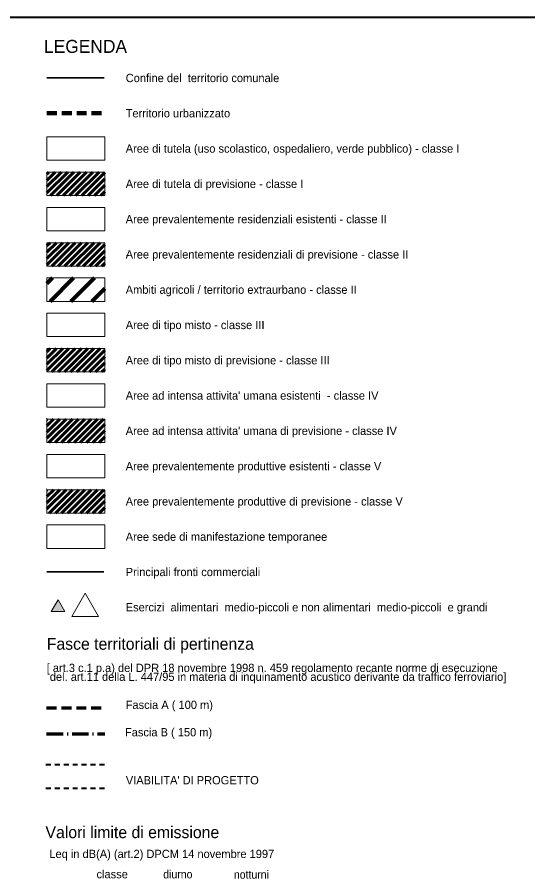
# Model space of a CAD drawing. Extents: x 650071 to 653841, y 889105 to 891996.
# Drawn here: x 651141 to 652006, y 890536 to 891996 of the extents above; entities that cross this region are included whole.
import ezdxf
from ezdxf.enums import TextEntityAlignment as Align

# ---------------------------------------------------------------- set-up
doc = ezdxf.new("R2010")
doc.units = 0
doc.header["$LTSCALE"] = 5.6
for name, pattern in [('DOT_DASHED', [7.7, 5, -1.2, 0.3, -1.2]), ('MEDIUM_DASHED', [4.5, 3, -1.5]), ('SHORT_DASHED', [2.7, 1.5, -1.2])]:
    doc.linetypes.add(name, pattern=pattern)
doc.layers.add('61', color=7, linetype='Continuous', lineweight=35)

msp = doc.modelspace()

# ---------------------------------------------------------------- hatches: boundary and pattern name
at = {"layer": '61'}
msp.add_hatch(color=256, dxfattribs=at).paths.add_polyline_path([(651209.89, 891008.04), (651221.26, 890988.36), (651198.51, 890988.36)])

# ---------------------------------------------------------------- linework, layer by layer
at = {"layer": '61', "lineweight": 40}
msp.add_line((651121.43, 891995.66), (652174.45, 891995.66), dxfattribs=at)
at = {"layer": '61'}
for p, q in [((651191.11, 891892.74), (651288.09, 891892.74)), ((651287.69, 891055.54), (651191.11, 891055.54))]:
    msp.add_line(p, q, dxfattribs=at)
at = {"layer": '61', "linetype": 'MEDIUM_DASHED', "lineweight": 100}
msp.add_line((651191.11, 891832.92), (651288.77, 891832.92), dxfattribs=at)
at = {"layer": '61', "lineweight": 60}
for p, q in [((651191.11, 891729.77), (651194.46, 891733.12)), ((651191.11, 891719.17), (651205.06, 891733.12)), ((651191.11, 891708.56), (651215.67, 891733.12)), ((651191.11, 891697.95), (651226.28, 891733.12)), ((651197.28, 891693.52), (651236.88, 891733.12)), ((651207.89, 891693.52), (651247.49, 891733.12)), ((651218.5, 891693.52), (651258.1, 891733.12)), ((651229.1, 891693.52), (651268.7, 891733.12)), ((651239.71, 891693.52), (651279.31, 891733.12)), ((651250.32, 891693.52), (651289.03, 891732.24)), ((651260.92, 891693.52), (651289.03, 891721.63)), ((651271.53, 891693.52), (651289.03, 891711.02)), ((651282.14, 891693.52), (651289.03, 891700.42)), ((651191.11, 891608), (651196.66, 891613.54)), ((651191.11, 891597.4), (651207.25, 891613.54)), ((651191.11, 891586.81), (651217.84, 891613.54)), ((651191.11, 891576.22), (651228.43, 891613.54)), ((651199.43, 891573.94), (651239.03, 891613.54)), ((651210.02, 891573.94), (651249.62, 891613.54)), ((651220.61, 891573.94), (651260.21, 891613.54)), ((651231.2, 891573.94), (651270.8, 891613.54)), ((651241.79, 891573.94), (651281.39, 891613.54)), ((651252.39, 891573.94), (651289.03, 891610.58)), ((651262.98, 891573.94), (651289.03, 891599.99)), ((651273.57, 891573.94), (651289.03, 891589.4)), ((651284.16, 891573.94), (651289.03, 891578.81)), ((651191.11, 891428.62), (651196.63, 891434.14)), ((651191.11, 891418.03), (651207.22, 891434.14)), ((651191.11, 891407.44), (651217.81, 891434.14)), ((651191.11, 891396.84), (651228.41, 891434.14)), ((651199.4, 891394.54), (651239, 891434.14)), ((651209.99, 891394.54), (651249.59, 891434.14)), ((651220.58, 891394.54), (651260.18, 891434.14)), ((651231.18, 891394.54), (651270.78, 891434.14)), ((651241.77, 891394.54), (651281.37, 891434.14)), ((651252.36, 891394.54), (651289.03, 891431.21)), ((651262.95, 891394.54), (651289.03, 891420.62)), ((651273.55, 891394.54), (651289.03, 891410.02)), ((651284.14, 891394.54), (651289.03, 891399.43)), ((651191.11, 891313.86), (651191.79, 891314.54)), ((651191.11, 891303.27), (651202.38, 891314.54)), ((651191.11, 891292.68), (651212.97, 891314.54)), ((651191.11, 891282.09), (651223.56, 891314.54)), ((651194.56, 891274.94), (651234.16, 891314.54)), ((651205.15, 891274.94), (651244.75, 891314.54)), ((651215.74, 891274.94), (651255.34, 891314.54)), ((651226.33, 891274.94), (651265.93, 891314.54)), ((651236.93, 891274.94), (651276.53, 891314.54)), ((651247.52, 891274.94), (651287.12, 891314.54)), ((651258.11, 891274.94), (651289.03, 891305.86)), ((651268.7, 891274.94), (651289.03, 891295.27)), ((651279.3, 891274.94), (651289.03, 891284.67)), ((651191.11, 891194.08), (651191.97, 891194.94)), ((651191.11, 891183.49), (651202.56, 891194.94)), ((651191.11, 891172.9), (651213.16, 891194.94)), ((651191.11, 891162.3), (651223.75, 891194.94)), ((651194.74, 891155.34), (651234.34, 891194.94)), ((651205.33, 891155.34), (651244.93, 891194.94)), ((651215.93, 891155.34), (651255.53, 891194.94)), ((651226.52, 891155.34), (651266.12, 891194.94)), ((651237.11, 891155.34), (651276.71, 891194.94)), ((651247.7, 891155.34), (651287.3, 891194.94)), ((651258.29, 891155.34), (651289.03, 891186.08)), ((651268.89, 891155.34), (651289.03, 891175.48)), ((651279.48, 891155.34), (651289.03, 891164.89))]:
    msp.add_line(p, q, dxfattribs=at)
at = {"layer": '61', "lineweight": 120}
for p, q in [((651191.11, 891544.21), (651200.67, 891553.77)), ((651196.43, 891514.17), (651236.03, 891553.77)), ((651231.78, 891514.17), (651271.38, 891553.77)), ((651267.14, 891514.17), (651289.03, 891536.06))]:
    msp.add_line(p, q, dxfattribs=at)
at = {"layer": '61', "linetype": 'MEDIUM_DASHED', "lineweight": 70}
msp.add_line((651190.61, 890824.99), (651289.03, 890824.99), dxfattribs=at)
at = {"layer": '61', "linetype": 'DOT_DASHED', "lineweight": 70}
msp.add_line((651190.61, 890781.27), (651289.03, 890781.27), dxfattribs=at)
at = {"layer": '61', "linetype": 'SHORT_DASHED', "lineweight": 40}
for p, q in [((651189.35, 890729), (651289.03, 890729)), ((651189.35, 890689), (651289.03, 890689))]:
    msp.add_line(p, q, dxfattribs=at)
at = {"layer": '61', "lineweight": 13}
for points in [[(651191.11, 891792.92), (651289.03, 891792.92), (651289.03, 891753.32), (651191.11, 891753.32)], [(651191.11, 891733.12), (651289.03, 891733.12), (651289.03, 891693.52), (651191.11, 891693.52)], [(651191.11, 891673.34), (651289.03, 891673.34), (651289.03, 891633.74), (651191.11, 891633.74)], [(651191.11, 891613.54), (651289.03, 891613.54), (651289.03, 891573.94), (651191.11, 891573.94)], [(651191.11, 891553.77), (651289.03, 891553.77), (651289.03, 891514.17), (651191.11, 891514.17)], [(651191.11, 891493.94), (651289.03, 891493.94), (651289.03, 891454.34), (651191.11, 891454.34)], [(651191.11, 891434.14), (651289.03, 891434.14), (651289.03, 891394.54), (651191.11, 891394.54)], [(651191.11, 891374.34), (651289.03, 891374.34), (651289.03, 891334.74), (651191.11, 891334.74)], [(651191.11, 891314.54), (651289.03, 891314.54), (651289.03, 891274.94), (651191.11, 891274.94)], [(651191.11, 891254.74), (651289.03, 891254.74), (651289.03, 891215.14), (651191.11, 891215.14)], [(651191.11, 891194.94), (651289.03, 891194.94), (651289.03, 891155.34), (651191.11, 891155.34)], [(651191.11, 891135.17), (651289.03, 891135.17), (651289.03, 891095.57), (651191.11, 891095.57)], [(651255.82, 891019.35), (651278.56, 890979.97), (651233.09, 890979.97)], [(651209.89, 891008.04), (651221.26, 890988.36), (651198.51, 890988.36)]]:
    msp.add_lwpolyline(points, close=True, dxfattribs=at)

# ---------------------------------------------------------------- texts
at = {"layer": '61'}
for s, height, p in [('LEGENDA', 22, (651186.16, 891935.25)), ('Confine del  territorio comunale  ', 14, (651324.51, 891885.68)), ('Territorio urbanizzato', 14, (651324.51, 891825.9)), ('Aree di tutela (uso scolastico, ospedaliero, verde pubblico) - classe I', 14, (651324.51, 891766.08)), ('Aree di tutela di previsione - classe I', 14, (651324.51, 891706.28)), ('Aree prevalentemente residenziali esistenti - classe II', 14, (651324.51, 891646.5)), ('Aree prevalentemente residenziali di previsione - classe II', 14, (651324.51, 891586.7)), ('-', 14.06, (651324.51, 891586.67)), ('Ambiti agricoli / territorio extraurbano - classe II', 14, (651324.51, 891526.93)), ('Aree di tipo misto - classe III', 14, (651324.51, 891467.1)), ('Aree di tipo misto di previsione - classe III', 14, (651324.51, 891407.3)), ("Aree ad intensa attivita' umana esistenti  - classe IV", 14, (651324.51, 891347.5)), ("Aree ad intensa attivita' umana di previsione - classe IV", 14, (651324.51, 891287.7)), ('Aree prevalentemente produttive esistenti - classe V', 14, (651324.51, 891227.9)), ('Aree prevalentemente produttive di previsione - classe V', 14, (651324.51, 891168.1)), ('Aree sede di manifestazione temporanee', 14, (651324.51, 891108.33)), ('Principali fronti commerciali', 14, (651324.51, 891048.5)), ('Esercizi  alimentari  medio-piccoli e non alimentari  medio-piccoli  e grandi', 14, (651324.51, 890988.7)), ('Fasce territoriali di pertinenza', 20, (651190.81, 890923.72)), ('[ art.3 c.1 p.a) del DPR 18 novembre 1998 n. 459 regolamento recante norme di esecuzione', 14, (651190.73, 890885.97)), (' del. art.11 della L. 447/95 in materia di inquinamento acustico derivante da traffico ferroviario]', 14, (651190.73, 890870.97)), ('Fascia A ( 100 m)', 14, (651324.51, 890823.36)), ('Fascia B ( 150 m)', 14, (651323.26, 890776.93)), ("VIABILITA' DI PROGETTO", 14, (651324.73, 890695.58)), ('Valori limite di emissione', 20, (651188.64, 890604.42)), ('Leq in dB(A) (art.2) DPCM 14 novembre 1997', 14, (651195.22, 890570.74))]:
    msp.add_text(s, height=height, dxfattribs=at).set_placement(p)
msp.add_text('classe', height=14, dxfattribs=at).set_placement((651301.63, 890536.42), align=Align.CENTER)
at = {"layer": '61', "width": 0.95}
for s, p in [('diurno', (651412.85, 890536.22)), ('notturni', (651537.41, 890535.78))]:
    msp.add_text(s, height=14, dxfattribs=at).set_placement(p, align=Align.CENTER)

doc.saveas('drawing.dxf')
